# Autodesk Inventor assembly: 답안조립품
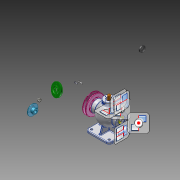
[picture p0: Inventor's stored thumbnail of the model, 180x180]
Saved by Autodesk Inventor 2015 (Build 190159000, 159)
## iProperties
Created: 2025-08
Part Number: 답안조립품
Document SubType Name: Assembly
Designer: USER
Author: USER
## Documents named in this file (15)
- C:\Users\USER\Desktop\750808V1014 (1)\답안조립품.iam
- C:\Users\USER\Desktop\750808V1014 (1)\가져온 구성요소\V-벨트풀리\V-벨트풀리.ipt
- C:\Users\USER\Desktop\750808V1014 (1)\가져온 구성요소\너트 M8\너트 M8.ipt
- C:\Users\USER\Desktop\750808V1014 (1)\가져온 구성요소\뒤커버\뒤커버.ipt
- C:\Users\USER\Desktop\750808V1014 (1)\가져온 구성요소\베어링- 6202\베어링- 6202.ipt
- C:\Users\USER\Desktop\750808V1014 (1)\가져온 구성요소\볼트 M4 x 12\볼트 M4 x 12.ipt
- C:\Users\USER\Desktop\750808V1014 (1)\가져온 구성요소\볼트 M4 x 16\볼트 M4 x 16.ipt
- C:\Users\USER\Desktop\750808V1014 (1)\가져온 구성요소\상부커버\상부커버.ipt
- C:\Users\USER\Desktop\750808V1014 (1)\가져온 구성요소\슬라이드\슬라이드.ipt
- C:\Users\USER\Desktop\750808V1014 (1)\가져온 구성요소\앞커버\앞커버.ipt
- C:\Users\USER\Desktop\750808V1014 (1)\가져온 구성요소\오일실 15 30 7\오일실 15 30 7.ipt
- C:\Users\USER\Desktop\750808V1014 (1)\가져온 구성요소\칼라\칼라.ipt
- C:\Users\USER\Desktop\750808V1014 (1)\가져온 구성요소\키 4 x 4 x 12\키 4 x 4 x 12.ipt
- C:\Users\USER\Desktop\750808V1014 (1)\가져온 구성요소\편심축\편심축.ipt
- C:\Users\USER\Desktop\750808V1014 (1)\본체.ipt
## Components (1 placed, 1 different names)
1. V-벨트풀리:1
